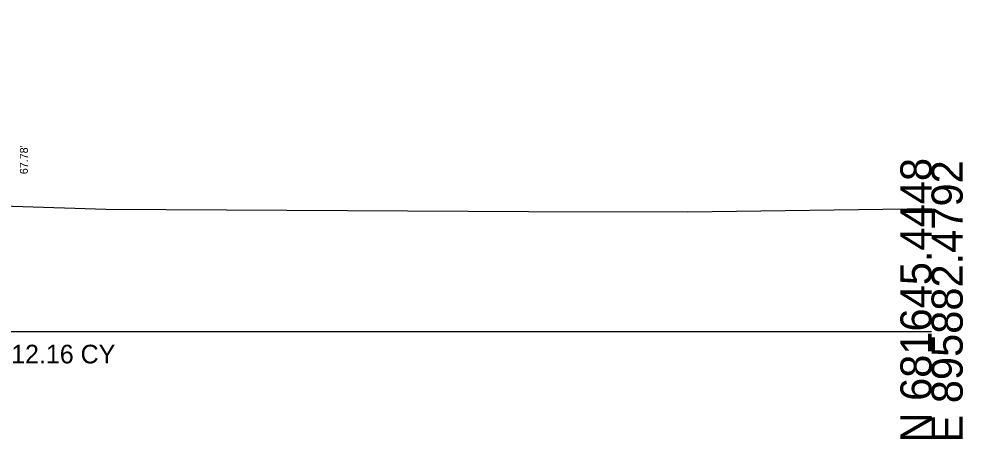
# Model space of a CAD drawing. Extents: x -26 to 4403, y -13 to 9578.
# Drawn here: x 3317.9 to 3402.8, y 8490.3 to 8528.1 of the extents above; entities that cross this region are included whole.
import ezdxf

# ---------------------------------------------------------------- set-up
doc = ezdxf.new("R2010")
doc.units = 0
for name, color, linetype in [('DTM_X_GROUND', 7, 'Continuous'), ('XS_CELL', 7, 'Continuous'), ('XS_P_TX_CLEARZONE', 7, 'Continuous'), ('XS_SHEET_EW_TX_VOLUME', 7, 'Continuous')]:
    doc.layers.add(name, color=color, linetype=linetype)

msp = doc.modelspace()

# ---------------------------------------------------------------- linework, layer by layer
at = {"layer": 'DTM_X_GROUND'}
msp.add_lwpolyline([(3153.808, 8513.95), (3170.909, 8514.966), (3177.153, 8518.209), (3197.118, 8527.209), (3198.789, 8527.5), (3201.713, 8527.882), (3210.312, 8528.066), (3213.777, 8528.123), (3216.864, 8528.039), (3224.572, 8527.826), (3225.877, 8527.605), (3229.562, 8526.928), (3236.992, 8522.323), (3249.998, 8515.154), (3250, 8515.153), (3250.751, 8515.018), (3252.885, 8514.328), (3255.752, 8514.055), (3262.783, 8513.146), (3270.679, 8512.757), (3325.754, 8511.013), (3363.759, 8510.776), (3378.096, 8510.765), (3400, 8511.068)], dxfattribs=at)
at = {"layer": 'XS_CELL'}
msp.add_line((3250, 8500), (3400, 8500), dxfattribs=at)

# ---------------------------------------------------------------- texts
for s, p in [('N 681645.4448', (3400, 8490)), ('E 895882.4792', (3402.8, 8490))]:
    msp.add_text(s, height=2.8, rotation=90, dxfattribs=at).set_placement(p)
at = {"layer": 'XS_P_TX_CLEARZONE'}
msp.add_text("67.78'", height=0.72, rotation=90, dxfattribs=at).set_placement((3318.741, 8514.149))
msp.add_text("67.78'", height=0.72, rotation=90, dxfattribs=at).set_placement((3318.741, 8514.149))
msp.add_text("67.78'", height=0.72, rotation=90, dxfattribs=at).set_placement((3318.741, 8514.149))
msp.add_text("67.78'", height=0.72, rotation=90, dxfattribs=at).set_placement((3318.741, 8514.149))
msp.add_text("67.78'", height=0.72, rotation=90, dxfattribs=at).set_placement((3318.741, 8514.149))
msp.add_text("67.78'", height=0.72, rotation=90, dxfattribs=at).set_placement((3318.741, 8514.149))
msp.add_text("67.78'", height=0.72, rotation=90, dxfattribs=at).set_placement((3318.741, 8514.149))
msp.add_text("67.78'", height=0.72, rotation=90, dxfattribs=at).set_placement((3318.741, 8514.149))
msp.add_text("67.78'", height=0.72, rotation=90, dxfattribs=at).set_placement((3318.741, 8514.149))
at = {"layer": 'XS_SHEET_EW_TX_VOLUME'}
msp.add_text('CV: 712.16 CY', height=1.68, dxfattribs=at).set_placement((3311.615, 8497.12))

doc.saveas('drawing.dxf')
